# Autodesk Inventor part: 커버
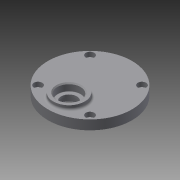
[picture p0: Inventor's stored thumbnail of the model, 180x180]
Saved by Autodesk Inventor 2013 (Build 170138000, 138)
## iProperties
Created: 2015-07
Part Number: 커버
Material: 일반
Document SubType Name: Modeling
Designer: user
Density: 1 g/cm^3
Author: user
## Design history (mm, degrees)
sketch "스케치1"
  geometry: C1 r 40 at (0, 0); 1 further point
  constraints: 1 centre point, 1 coincident
  dimensions: "d0" = 40 radius of C1
extrude "돌출1" new body sketch "스케치1" distance "d1" = 9; taper "d2" = 0 deg
sketch "스케치2"
  geometry: L1 (0, 0)-(0, -20); C1 r 40 at (0, 0) reference; C2 r 15 at (0, -20)
  constraints: 2 end point, 1 centre point, 1 coincident, 1 vertical
  dimensions: "d3" = 20 distance of L1.start L1.end; "d4" = 15 radius of C2
extrude "돌출2" join sketch "스케치2" distance "d5" = 4; taper "d6" = 0 deg
sketch "스케치3"
  geometry: L1 (0, 0)-(0, 11); L2 (0, 0)-(0, -20); C1 r 40 at (0, 0) reference; C2 r 14 at (0, 11); C3 r 14 at (0, -20)
  constraints: 4 end point, 2 centre point, 2 coincident, 1 collinear, 1 vertical
  dimensions: "d7" = 11 distance of L1.start L1.end; "d8" = 20 distance of L1.start L2.end; "d9" = 14 radius of C2; "d10" = 14 radius of C3
extrude "돌출3" join sketch "스케치3" distance "d11" = 3; taper "d12" = 0 deg
sketch "스케치4"
  geometry: C1 r 15 at (0, 0) reference; 1 further point
hole "구멍1" sketch "스케치4" at (0, 0) diameter "d13" = 15; stored, may be unused: countersink angle "d17" = 90 deg, drill point angle "d19" = 0 deg; dims "d14" = 6, "d15" = 22, "d16" = 7, "d18" = 9
sketch "스케치5"
  geometry: C1 r 14 at (0, 0) reference; 1 further point
hole "구멍2" sketch "스케치5" at (0, 0) diameter "d20" = 22; stored, may be unused: countersink angle "d24" = 90 deg, drill point angle "d26" = 0 deg; dims "d21" = 6, "d22" = 22, "d23" = 7, "d25" = 7
sketch "스케치6"
  geometry: C1 r 14 at (0, 0) reference; 1 further point
hole "구멍3" sketch "스케치6" at (0, 0) diameter "d27" = 18; stored, may be unused: countersink angle "d31" = 90 deg, drill point angle "d33" = 0 deg; dims "d28" = 6, "d29" = 22, "d30" = 7, "d32" = 8
chamfer "모따기1" distance "d34" = 1; stored, may be unused: second distance "d35" = 2, angle "d36" = 45 deg
fillet "모깎기1" dims "d37" = 0.3
fillet "모깎기2" dims "d38" = 2
fillet "모깎기3" dims "d39" = 0.3
sketch "스케치7"
  geometry: C1 r 40 at (0, 0) reference; 4 further points
  constraints: 5 other
  dimensions: "d43" = 360 deg dimension on C1.centre point (-24.749, 24.749) (derived)
hole "구멍4" sketch "스케치7" at (-24.749, 24.749), (-24.749, -24.749), (24.749, -24.749), (24.749, 24.749) diameter "d45" = 4.5; stored, may be unused: countersink angle "d49" = 90 deg, drill point angle "d51" = 0 deg; dims "d46" = 6, "d47" = 8, "d48" = 4.4, "d50" = 8
fillet "모깎기4" dims "d52" = 2
node "솔리드1"
